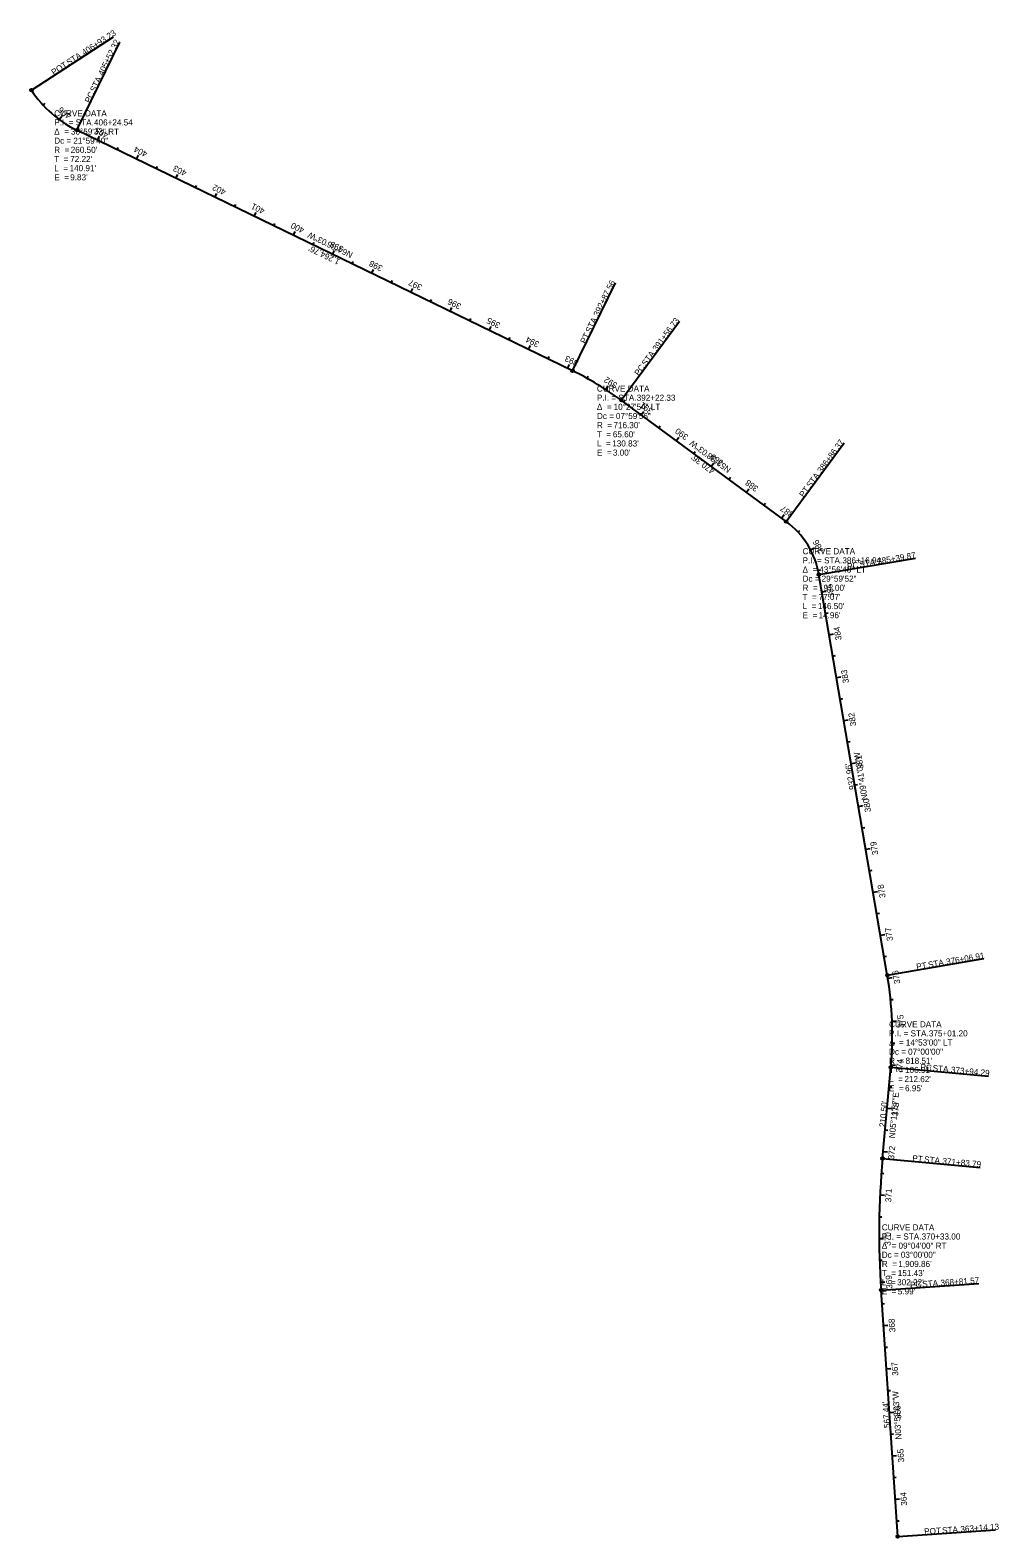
# Model space of a CAD drawing. Extents: x 110322 to 112545, y 428347 to 431810.
import ezdxf

# ---------------------------------------------------------------- set-up
doc = ezdxf.new("R2010")
doc.units = 0
for name, color, linetype in [('GE_P_Alignment_100_Bearings', 7, 'Continuous'), ('GE_P_Alignment_100_Cardinal_Points', 7, 'Continuous'), ('GE_P_Alignment_100_Curve_Data', 7, 'Continuous'), ('GE_P_Alignment_100_Distances', 7, 'Continuous'), ('GE_P_Alignment_100_Stations', 7, 'Continuous'), ('RW_X_CL', 7, 'Continuous')]:
    doc.layers.add(name, color=color, linetype=linetype)

msp = doc.modelspace()

# ---------------------------------------------------------------- linework, layer by layer
at = {"layer": 'GE_P_Alignment_100_Cardinal_Points'}
for p, q in [((110324.6, 431671.8), (110513.1, 431794.7)), ((110429, 431579.8), (110527.3, 431782.2)), ((111566.7, 431027.3), (111665, 431229.7)), ((111678.6, 430959.8), (111812, 431141)), ((112057.3, 430680.9), (112190.7, 430862.1)), ((112132.3, 430559.2), (112354.1, 430597.1)), ((112289.3, 429639.5), (112511.1, 429677.4)), ((112297.6, 429427.7), (112521.6, 429407.3)), ((112278.5, 429218.1), (112502.6, 429197.7)), ((112275, 428916.2), (112499.5, 428931.3)), ((112313.3, 428350), (112537.8, 428365.2))]:
    msp.add_line(p, q, dxfattribs=at)
for centre in [(110324.6, 431671.8), (110429, 431579.8), (111566.7, 431027.3), (111678.6, 430959.8), (112057.3, 430680.9), (112132.3, 430559.2), (112289.3, 429639.5), (112297.6, 429427.7), (112278.5, 429218.1), (112275, 428916.2), (112313.3, 428350)]:
    msp.add_circle(centre, 3, dxfattribs=at)
at = {"layer": 'GE_P_Alignment_100_Stations'}
for p, q in [((110351.1, 431637.7), (110355.5, 431641.8)), ((110388.3, 431604.4), (110394.2, 431612.4)), ((110431.1, 431578.7), (110433.7, 431584.1)), ((110476.1, 431556.9), (110480.4, 431565.9)), ((110521, 431535.1), (110523.7, 431540.5)), ((110566, 431513.2), (110570.4, 431522.2)), ((110611, 431491.4), (110613.6, 431496.8)), ((110656, 431469.5), (110660.3, 431478.5)), ((110701, 431447.7), (110703.6, 431453.1)), ((110745.9, 431425.9), (110750.3, 431434.9)), ((110790.9, 431404), (110793.5, 431409.4)), ((110835.9, 431382.2), (110840.3, 431391.2)), ((110880.9, 431360.3), (110883.5, 431365.7)), ((110925.8, 431338.5), (110930.2, 431347.5)), ((110970.8, 431316.7), (110973.4, 431322.1)), ((111015.8, 431294.8), (111020.2, 431303.8)), ((111060.8, 431273), (111063.4, 431278.4)), ((111105.8, 431251.2), (111110.1, 431260.1)), ((111150.7, 431229.3), (111153.4, 431234.7)), ((111195.7, 431207.5), (111200.1, 431216.5)), ((111240.7, 431185.6), (111243.3, 431191)), ((111285.7, 431163.8), (111290, 431172.8)), ((111330.7, 431142), (111333.3, 431147.4)), ((111375.6, 431120.1), (111380, 431129.1)), ((111420.6, 431098.3), (111423.2, 431103.7)), ((111465.6, 431076.4), (111470, 431085.4)), ((111510.6, 431054.6), (111513.2, 431060)), ((111555.5, 431032.8), (111559.9, 431041.8)), ((111600.1, 431010), (111603, 431015.3)), ((111643, 430984.4), (111648.4, 430992.8)), ((111684, 430955.8), (111687.5, 430960.6)), ((111724.2, 430926.1), (111730.2, 430934.2)), ((111764.5, 430896.5), (111768.1, 430901.3)), ((111804.8, 430866.8), (111810.7, 430874.9)), ((111845, 430837.2), (111848.6, 430842)), ((111885.3, 430807.5), (111891.2, 430815.6)), ((111925.6, 430777.9), (111929.1, 430782.7)), ((111965.8, 430748.3), (111971.8, 430756.3)), ((112006.1, 430718.6), (112009.6, 430723.4)), ((112046.3, 430689), (112052.3, 430697)), ((112084.4, 430656.7), (112088.8, 430660.7)), ((112113.1, 430615.9), (112122, 430620.6)), ((112130.4, 430569.1), (112136.2, 430570.5)), ((112139, 430519.9), (112148.9, 430521.6)), ((112147.5, 430470.6), (112153.4, 430471.6)), ((112155.9, 430421.3), (112165.7, 430423)), ((112164.3, 430372), (112170.2, 430373.1)), ((112172.7, 430322.8), (112182.5, 430324.4)), ((112181.1, 430273.5), (112187, 430274.5)), ((112189.5, 430224.2), (112199.4, 430225.9)), ((112197.9, 430174.9), (112203.8, 430175.9)), ((112206.3, 430125.6), (112216.2, 430127.3)), ((112214.7, 430076.3), (112220.7, 430077.3)), ((112223.2, 430027), (112233, 430028.7)), ((112231.6, 429977.7), (112237.5, 429978.8)), ((112240, 429928.5), (112249.8, 429930.1)), ((112248.4, 429879.2), (112254.3, 429880.2)), ((112256.8, 429829.9), (112266.7, 429831.6)), ((112265.2, 429780.6), (112271.1, 429781.6)), ((112273.6, 429731.3), (112283.5, 429733)), ((112282, 429682), (112287.9, 429683)), ((112290.4, 429632.7), (112300.3, 429634.3)), ((112296.9, 429583.2), (112302.9, 429583.8)), ((112300.3, 429533.3), (112310.3, 429533.7)), ((112300.7, 429483.3), (112306.7, 429483.2)), ((112298.1, 429433.4), (112308, 429432.5)), ((112293.6, 429383.6), (112299.5, 429383)), ((112289, 429333.8), (112299, 429332.9)), ((112284.5, 429284), (112290.5, 429283.4)), ((112280, 429234.2), (112289.9, 429233.3)), ((112275.7, 429184.4), (112281.7, 429183.9)), ((112272.7, 429134.5), (112282.7, 429134)), ((112271.1, 429084.5), (112277.1, 429084.4)), ((112270.7, 429034.5), (112280.7, 429034.6)), ((112271.6, 428984.5), (112277.6, 428984.7)), ((112273.8, 428934.6), (112283.8, 428935.1)), ((112277.1, 428884.7), (112283.1, 428885.1)), ((112280.5, 428834.8), (112290.5, 428835.5)), ((112283.9, 428784.9), (112289.9, 428785.3)), ((112287.2, 428735), (112297.2, 428735.7)), ((112290.6, 428685.1), (112296.6, 428685.5)), ((112294, 428635.2), (112304, 428635.9)), ((112297.4, 428585.4), (112303.3, 428585.8)), ((112300.7, 428535.5), (112310.7, 428536.1)), ((112304.1, 428485.6), (112310.1, 428486)), ((112307.5, 428435.7), (112317.5, 428436.4)), ((112310.8, 428385.8), (112316.8, 428386.2))]:
    msp.add_line(p, q, dxfattribs=at)
at = {"layer": 'RW_X_CL'}
for p, q in [((111566.7, 431027.3), (110429, 431579.8)), ((112057.3, 430680.9), (111678.6, 430959.8)), ((112289.3, 429639.5), (112132.3, 430559.2)), ((112278.5, 429218.1), (112297.6, 429427.7)), ((112313.3, 428350), (112275, 428916.2))]:
    msp.add_line(p, q, dxfattribs=at)
for centre, radius, start, end in [((110542.8, 431814.1), 260.5, 213.1083, 244.1008), ((111253.8, 430383), 716.3, 53.6341, 64.099), ((111944.1, 430527.1), 191, 9.6841, 53.6309), ((111482.4, 429501.9), 818.5, 354.8008, 9.6842), ((114180.5, 429045), 1909.9, 174.8009, 183.8675)]:
    msp.add_arc(centre, radius, start, end, dxfattribs=at)

# ---------------------------------------------------------------- texts
at = {"layer": 'GE_P_Alignment_100_Bearings'}
for s, rotation, p in [('N64°06\'03"W', 154.1008, (111063.7, 431298.2)), ('N53°38\'03"W', 143.6341, (111931.8, 430803.1)), ('N09°41\'03"W', 99.6841, (112244.8, 430042.7)), ('N05°11\'57"E', 84.8008, (112306.8, 429264.1)), ('N03°52\'03"W', 93.8675, (112322.2, 428573.3))]:
    msp.add_text(s, height=14, rotation=rotation, dxfattribs=at).set_placement(p)
at = {"layer": 'GE_P_Alignment_100_Cardinal_Points'}
for s, rotation, p in [('406+93.23', 33.1083, (110445.6, 431751)), ('405+52.32', 64.1008, (110489.1, 431704)), ('POT', 33.1083, (110375.9, 431705.5)), (' STA. ', 33.1083, (110406, 431725.2)), (' STA. ', 64.1008, (110468.5, 431661.5)), ('PC', 64.1008, (110458.5, 431640.9)), ('392+87.56', 64.1008, (111626.5, 431150.9)), (' STA. ', 64.1008, (111605.9, 431108.4)), ('391+56.73', 53.6341, (111760.3, 431071.1)), ('PT', 64.1008, (111596.2, 431088.5)), (' STA. ', 53.6341, (111732.3, 431033.1)), ('PC', 53.6341, (111718.7, 431014.6)), ('386+86.37', 53.6341, (112138.4, 430791.3)), ('PT', 53.6341, (112097.2, 430735.5)), (' STA. ', 53.6341, (112110.3, 430753.2)), ('PC', 9.6841, (112198.5, 430570.7)), (' STA. ', 9.6841, (112221.1, 430574.6)), ('385+39.87', 9.6841, (112267.7, 430582.5)), ('376+06.91', 9.6841, (112425.6, 429663)), ('PT', 9.6841, (112357.2, 429651.4)), (' STA. ', 9.6841, (112379, 429655.1)), ('PC', 354.8008, (112365, 429421.8)), (' STA. ', 354.8008, (112387.8, 429419.7)), ('373+94.29', 354.8008, (112434.9, 429415.4)), ('PT', 354.8008, (112346.3, 429212.1)), (' STA. ', 354.8008, (112368.3, 429210.1)), ('371+83.79', 354.8008, (112415.4, 429205.8)), ('PC', 3.8675, (112342, 428920.9)), (' STA. ', 3.8675, (112364.9, 428922.5)), ('368+81.57', 3.8675, (112412, 428925.6)), ('POT', 3.8675, (112374.5, 428354.4)), (' STA. ', 3.8675, (112410.4, 428356.8)), ('363+14.13', 3.8675, (112457.6, 428360))]:
    msp.add_text(s, height=14, rotation=rotation, dxfattribs=at).set_placement(p)
at = {"layer": 'GE_P_Alignment_100_Curve_Data'}
for s, p in [('CURVE DATA', (110376.8, 431611.8)), ('P.I. = STA. ', (110376.8, 431590.8)), ('406+24.54', (110468.1, 431590.8)), ('Δ  = ', (110376.8, 431569.8)), ('Dc = ', (110376.8, 431548.8)), ('30°59\'33" RT', (110415.2, 431569.8)), ('21°59\'40"', (110420.5, 431548.8)), ('T  = ', (110376.8, 431506.8)), ('R  = ', (110376.8, 431527.8)), ("72.22'", (110413.5, 431506.8)), ("260.50'", (110414.7, 431527.8)), ('L  = ', (110376.8, 431485.8)), ("140.91'", (110412, 431485.8)), ('E  = ', (110376.8, 431464.8)), ("9.83'", (110413.5, 431464.8)), ('CURVE DATA', (111622.7, 430979.5)), ('P.I. = STA. ', (111622.7, 430958.5)), ('392+22.33', (111714, 430958.5)), ('Δ  = ', (111622.7, 430937.5)), ('Dc = ', (111622.7, 430916.5)), ('10°27\'54" LT', (111661, 430937.5)), ('07°59\'56"', (111666.3, 430916.5)), ('R  = ', (111622.7, 430895.5)), ("716.30'", (111660.6, 430895.5)), ('T  = ', (111622.7, 430874.5)), ('L  = ', (111622.7, 430853.5)), ("130.83'", (111657.9, 430853.5)), ("65.60'", (111659.3, 430874.5)), ('E  = ', (111622.7, 430832.5)), ("3.00'", (111659.4, 430832.5)), ('CURVE DATA', (112094.8, 430606)), ('P.I. = STA. ', (112094.8, 430585)), ('386+16.94', (112186.2, 430585)), ('Δ  = ', (112094.8, 430564)), ('Dc = ', (112094.8, 430543)), ('43°56\'48" LT', (112133.2, 430564)), ('29°59\'52"', (112138.5, 430543)), ('T  = ', (112094.8, 430501)), ('R  = ', (112094.8, 430522)), ("77.07'", (112131.5, 430501)), ("191.00'", (112132.7, 430522)), ('L  = ', (112094.8, 430480)), ("146.50'", (112130, 430480)), ('E  = ', (112094.8, 430459)), ("14.96'", (112131.5, 430459)), ('CURVE DATA', (112293.4, 429519.6)), ('P.I. = STA. ', (112293.4, 429498.6)), ('375+01.20', (112384.8, 429498.6)), ('Δ  = ', (112293.4, 429477.6)), ('14°53\'00" LT', (112331.8, 429477.6)), ('Dc = ', (112293.4, 429456.6)), ('R  = ', (112293.4, 429435.6)), ("818.51'", (112331.3, 429435.6)), ('07°00\'00"', (112337.1, 429456.6)), ('T  = ', (112293.4, 429414.6)), ('L  = ', (112293.4, 429393.6)), ("212.62'", (112328.6, 429393.6)), ("106.91'", (112330.1, 429414.6)), ('E  = ', (112293.4, 429372.6)), ("6.95'", (112330.1, 429372.6)), ('CURVE DATA', (112276.7, 429053.1)), ('Δ  = ', (112276.7, 429011.1)), ('P.I. = STA. ', (112276.7, 429032.1)), ('09°04\'00" RT', (112315.1, 429011.1)), ('370+33.00', (112368.1, 429032.1)), ('Dc = ', (112276.7, 428990.1)), ('03°00\'00"', (112320.4, 428990.1)), ('T  = ', (112276.7, 428948.1)), ('R  = ', (112276.7, 428969.1)), ("151.43'", (112313.4, 428948.1)), ("1,909.86'", (112314.7, 428969.1)), ('L  = ', (112276.7, 428927.1)), ("302.22'", (112312, 428927.1)), ('E  = ', (112276.7, 428906.1)), ("5.99'", (112313.4, 428906.1))]:
    msp.add_text(s, height=14, dxfattribs=at).set_placement(p)
at = {"layer": 'GE_P_Alignment_100_Distances'}
for s, rotation, p in [("1,264.76'", 154.1008, (111034.1, 431282.5)), ("470.36'", 143.6341, (111894.7, 430800.4)), ("932.96'", 99.6841, (112216.2, 430066.4)), ("210.50'", 84.8008, (112284.8, 429289.6)), ("567.44'", 93.8675, (112296.2, 428599.8))]:
    msp.add_text(s, height=14, rotation=rotation, dxfattribs=at).set_placement(p)
at = {"layer": 'GE_P_Alignment_100_Stations'}
for s, rotation, p in [('406', 143.6138, (110417.5, 431615.8)), ('405', 154.1008, (110502.5, 431573.5)), ('404', 154.1008, (110592.3, 431529.9)), ('403', 154.1008, (110682.3, 431486.2)), ('402', 154.1008, (110772.3, 431442.5)), ('401', 154.1008, (110861.6, 431399.1)), ('400', 154.1008, (110952.5, 431355)), ('399', 154.1008, (111042.3, 431311.4)), ('398', 154.1008, (111132.3, 431267.7)), ('397', 154.1008, (111222.7, 431223.9)), ('396', 154.1008, (111312.4, 431180.3)), ('395', 154.1008, (111402.1, 431136.7)), ('394', 154.1008, (111491.9, 431093.1)), ('393', 154.1008, (111581.8, 431049.5)), ('392', 147.0952, (111671.1, 430997.7)), ('391', 143.6341, (111752.6, 430938.1)), ('390', 143.6341, (111834, 430878.3)), ('389', 143.6341, (111914.4, 430819)), ('388', 143.6341, (111995, 430759.7)), ('387', 143.6341, (112075.8, 430700.2)), ('386', 117.7218, (112144.4, 430613.4)), ('385', 99.6841, (112167.9, 430508.1)), ('384', 99.6841, (112184.7, 430409.7)), ('383', 99.6841, (112201.6, 430311.1)), ('382', 99.6841, (112218.4, 430212.5)), ('381', 99.6841, (112235.1, 430114.5)), ('380', 99.6841, (112252.1, 430015)), ('379', 99.6841, (112268.9, 429916.6)), ('378', 99.6841, (112285.7, 429817.9)), ('377', 99.6841, (112302.6, 429718.9)), ('376', 99.2005, (112319.3, 429620.4)), ('375', 92.2005, (112327.5, 429517.8)), ('374', 85.2005, (112323.1, 429414.9)), ('373', 84.8008, (112313.9, 429315.1)), ('372', 84.8008, (112304.9, 429215.5)), ('371', 87.3146, (112298.5, 429117.5)), ('370', 90.3146, (112297.3, 429017.9)), ('369', 93.3146, (112301.3, 428919.5)), ('368', 93.8675, (112308.1, 428819.9)), ('367', 93.8675, (112314.8, 428719.8)), ('366', 93.8675, (112321.6, 428620.3)), ('365', 93.8675, (112328.3, 428520.8)), ('364', 93.8675, (112335, 428421.2))]:
    msp.add_text(s, height=14, rotation=rotation, dxfattribs=at).set_placement(p)

doc.saveas('drawing.dxf')
